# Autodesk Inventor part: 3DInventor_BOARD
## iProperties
Created: 2006-11
Part Number: 3DInventor_BOARD
Document SubType Name: Modeling
Designer: conardl1
Density: 1 g/cm^3
DESCRIPTION: Printed Circuit Board
MODELED_BY: L Conard
Author: conardl1
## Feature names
1. Base1
